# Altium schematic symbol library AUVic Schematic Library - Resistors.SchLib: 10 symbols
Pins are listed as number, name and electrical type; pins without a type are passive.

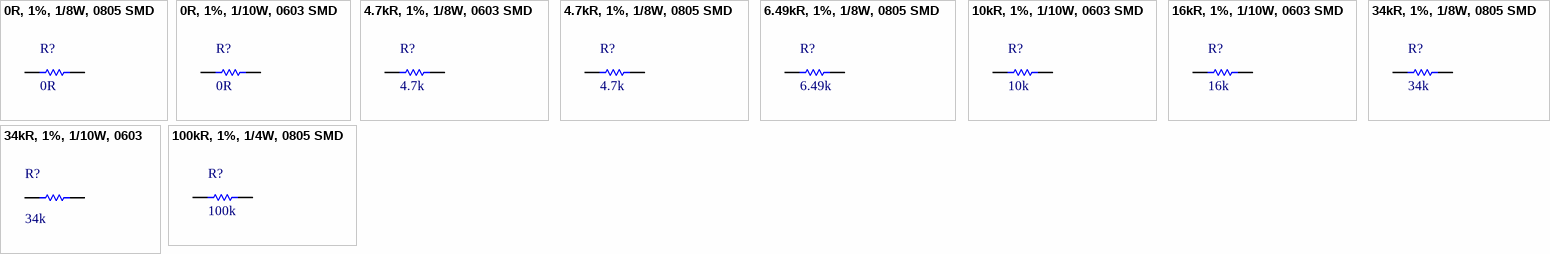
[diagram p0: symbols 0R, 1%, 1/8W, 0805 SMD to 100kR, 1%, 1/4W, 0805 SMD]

## 0R, 1%, 1/8W, 0805 SMD
designator R?, comment 0R
0R, 1%, 1/8W, 0805 SMD; Made By: Ashwin Sira; Owned By: AUVic
footprint RESC2012N(0805") (Chip Resistor, Body 2.0x1.3mm (0805"), IPC Medium Density)
pins: 1, 2

## 0R, 1%, 1/10W, 0603 SMD
designator R?, comment 0R
0R, 1%, 1/10W, 0603 SMD; Made By: Ashwin Sira; Owned By: AUVic
footprint RESC1608N(0603") (Chip Resistor, Body 1.6x0.8mm (0603"), IPC Medium Density)
pins: 1, 2

## 4.7kR, 1%, 1/8W, 0603 SMD
designator R?, comment 4.7k
4.7kR, 1%, 1/8W, 0603 SMD; Made By: Ashwin Sira; Owned By: AUVic
footprint RESC1608N(0603") (Chip Resistor, Body 1.6x0.8mm (0603"), IPC Medium Density)
pins: 1, 2

## 4.7kR, 1%, 1/8W, 0805 SMD
designator R?, comment 4.7k
4.7kR, 1%, 1/8W, 0805 SMD; Made By: Ashwin Sira; Owned By: AUVic
footprint RESC2012N(0805") (Chip Resistor, Body 2.0x1.3mm (0805"), IPC Medium Density)
pins: 1, 2

## 6.49kR, 1%, 1/8W, 0805 SMD
designator R?, comment 6.49k
6.49kR, 1%, 1/8W, 0805 SMD; Made By: Ashwin Sira; Owned By: AUVic
footprint RESC2012N(0805") (Chip Resistor, Body 2.0x1.3mm (0805"), IPC Medium Density)
pins: 1, 2

## 10kR, 1%, 1/10W, 0603 SMD
designator R?, comment 10k
10kR, 1%, 1/10W, 0603 SMD; Made By: Ashwin Sira; Owned By: AUVic
footprint RESC1608N(0603") (Chip Resistor, Body 1.6x0.8mm (0603"), IPC Medium Density)
pins: 1, 2

## 16kR, 1%, 1/10W, 0603 SMD
designator R?, comment 16k
16kR, 1%, 1/10W, 0603 SMD; Made By: Ashwin Sira; Owned By: AUVic
footprint RESC1608N(0603") (Chip Resistor, Body 1.6x0.8mm (0603"), IPC Medium Density)
pins: 1, 2

## 34kR, 1%, 1/8W, 0805 SMD
designator R?, comment 34k
34kR, 1%, 1/8W, 0805 SMD; Made By: Ashwin Sira; Owned By: AUVic
footprint RESC2012N(0805") (Chip Resistor, Body 2.0x1.3mm (0805"), IPC Medium Density)
pins: 1, 2

## 34kR, 1%, 1/10W, 0603
designator R?, comment 34k
RES 34K OHM 1/10W 1% 0603 SMD; Manufacturer: Yageo; Manufacturer Part Number: RC0603FR-0734KL; Power (Watts): 0.1W, 1/10W; Temperature Coefficient: ±100ppm/°C
footprint RESC1608N(0603") (Chip Resistor, Body 1.6x0.8mm (0603"), IPC Medium Density)
pins: 1, 2

## 100kR, 1%, 1/4W, 0805 SMD
designator R?, comment 100k
100kR, 1%, 1/4W, 0805 SMD; Made By: Ashwin Sira; Owned By: AUVic
footprint RESC2012N(0805") (Chip Resistor, Body 2.0x1.3mm (0805"), IPC Medium Density)
pins: 1, 2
